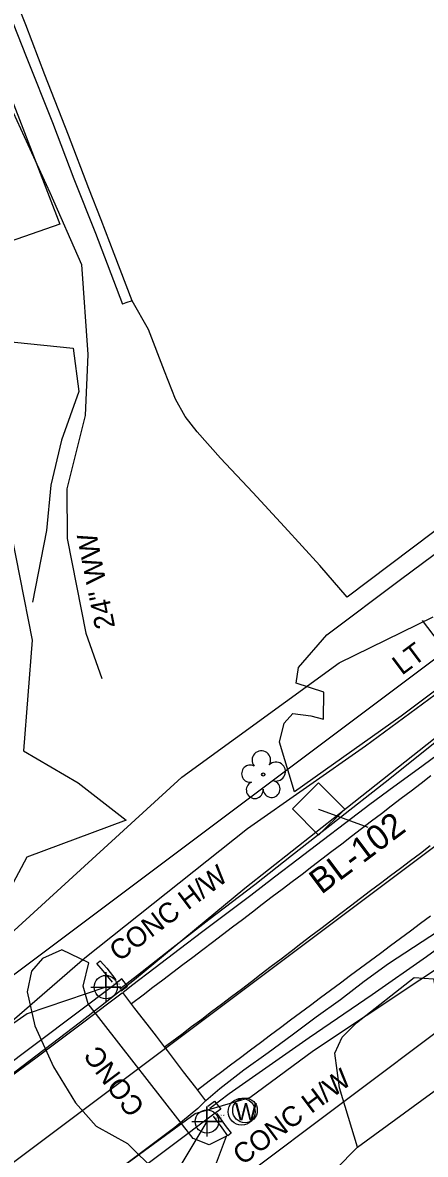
# Model space of a CAD drawing. Extents: x 2186615 to 2188822, y 629899 to 631820.
# Drawn here: x 2187814 to 2187894.7, y 630886.3 to 631112.9 of the extents above; entities that cross this region are included whole.
import ezdxf

# ---------------------------------------------------------------- set-up
doc = ezdxf.new("R2010")
doc.units = 0
for name, color, linetype in [('CTL Secondary Horizontal and Vertical CELL', 7, 'Continuous'), ('CTL Secondary Horizontal and Vertical Text', 7, 'Continuous'), ('CTL Vertical Benchmark Leader', 7, 'Continuous'), ('Exist Guardrail', 7, 'Continuous'), ('Exist Horizontal Alignment', 7, 'Continuous'), ('Exist Other Culture Area Outline', 7, 'Continuous'), ('Exist Other Culture Area Outline Text', 7, 'Continuous'), ('Exist Other Culture Fence Line', 7, 'Continuous'), ('Exist Other Culture Fence Line Text', 7, 'Continuous'), ('Exist Right of Way Line', 7, 'Continuous'), ('Exist Roads Curbs', 7, 'Continuous'), ('Exist Roads EOP', 7, 'Continuous'), ('Exist Roads EOP Other', 7, 'Continuous'), ('Exist Roads EOT', 7, 'Continuous'), ('Exist Structure Major Bridge Seat Cogo Point CELL', 7, 'Continuous'), ('Exist Structure Major Bridge Seat Leader', 7, 'Continuous'), ('Exist Structure Major Bridge WW', 7, 'Continuous'), ('Exist Structure Major Bridge WW Cogo Comment', 7, 'Continuous'), ('Exist Structure Major Bridge WW Text', 7, 'Continuous'), ('Exist Structure Major Deck Tunnel Box Culvert', 7, 'Continuous'), ('Exist Utilities Gas UG Line SUE LOS B', 7, 'Continuous'), ('Exist Utilities Power Pole CELL', 7, 'Continuous'), ('Exist Utilities Power Pole Text', 7, 'Continuous'), ('Exist Utilities Sanitary Sewer Forced Main SUE LOS B', 7, 'Continuous'), ('Exist Utilities Telephone UG FO SUE LOS B', 7, 'Continuous'), ('Exist Utilities Water Manhole CELL', 7, 'Continuous'), ('Exist Utilities Water UG Line SUE LOS B', 7, 'Continuous'), ('Exist Vegetation Hedge Row', 7, 'Continuous'), ('Exist Vegetation Tree CELL', 7, 'Continuous'), ('Exist Vegetation Woods Line', 7, 'Continuous')]:
    doc.layers.add(name, color=color, linetype=linetype)

msp = doc.modelspace()

# ---------------------------------------------------------------- linework, layer by layer
at = {"layer": 'CTL Secondary Horizontal and Vertical CELL'}
msp.add_line((2187873.29, 630955.43), (2187873.29, 630955.43), dxfattribs=at)
msp.add_lwpolyline([(2187868.08, 630955.45), (2187873.32, 630960.69), (2187878.57, 630955.44), (2187873.33, 630950.2)], close=True, dxfattribs=at)
at = {"layer": 'CTL Vertical Benchmark Leader'}
msp.add_line((2187873.29, 630955.43), (2187883.19, 630951.78), dxfattribs=at)
at = {"layer": 'Exist Guardrail'}
for points in [[(2188042.59, 631032.9), (2188030.54, 631024.16), (2188016.07, 631013.69), (2188000.23, 631002.25), (2187980.63, 630988.06), (2187964.45, 630976.33), (2187945.19, 630962.3), (2187928.74, 630950.37), (2187912, 630938.23), (2187894.95, 630925.87), (2187884.09, 630918.25), (2187871.47, 630909.61), (2187859.4, 630901.23), (2187855.44, 630898.44), (2187851.53, 630895.46)], [(2187833.49, 630919.46), (2187837.07, 630922.2), (2187843.61, 630927.3), (2187851.34, 630933.3), (2187860.56, 630940.3), (2187867.93, 630946.1), (2187876.17, 630952.6), (2187887.64, 630961.57), (2187898.7, 630970.45), (2187913.98, 630982.76), (2187928.97, 630994.69), (2187939.72, 631003.5)]]:
    msp.add_lwpolyline(points, dxfattribs=at)
at = {"layer": 'Exist Horizontal Alignment'}
msp.add_line((2187136.41, 630378.11), (2188520.86, 631416.04), dxfattribs=at)
at = {"layer": 'Exist Other Culture Area Outline'}
for points in [[(2187750.73, 631131.73), (2187754.38, 631137.93), (2187762.75, 631146.44), (2187787.59, 631158.3), (2187791.85, 631141.33), (2187804.46, 631116.53), (2187821.46, 631072.54), (2187791.35, 631062.08), (2187778.49, 631068.35), (2187771.08, 631115.01), (2187750.73, 631131.73)], [(2187821.88, 630927.25), (2187817.99, 630925.54), (2187815.81, 630923), (2187814.96, 630918.81), (2187816.47, 630912.02), (2187820.24, 630903.82), (2187824.62, 630896.62), (2187828.79, 630891.96), (2187835.07, 630888.46), (2187840.78, 630882.77), (2187850.88, 630879.29), (2187854.91, 630889.95), (2187851.43, 630888.23), (2187848.23, 630889.48), (2187827.14, 630916.4), (2187826.15, 630919.95), (2187827.29, 630924.63), (2187821.88, 630927.25)], [(2187835.03, 630919.99), (2187833.88, 630921.43), (2187832.7, 630920.52)], [(2187852.49, 630896.95), (2187853.72, 630895.32), (2187852.33, 630894.37)]]:
    msp.add_lwpolyline(points, dxfattribs=at)
msp.add_circle((2187858.59, 630895.1), 2.47, dxfattribs=at)
at = {"layer": 'Exist Other Culture Fence Line'}
msp.add_lwpolyline([(2187792.58, 631147.74), (2187801.82, 631123.05), (2187808.4, 631102.87), (2187819.45, 631078.84), (2187825.81, 631064.45), (2187827.07, 631046.46), (2187826.56, 631034.21), (2187822.88, 631019.53), (2187822.94, 631009.61), (2187826.72, 630990.63), (2187829.88, 630981.56)], dxfattribs=at)
at = {"layer": 'Exist Right of Way Line'}
for p, q in [((2187118.41, 630402.11), (2188502.83, 631440.02)), ((2187154.4, 630354.1), (2188538.85, 631392.04))]:
    msp.add_line(p, q, dxfattribs=at)
at = {"layer": 'Exist Roads Curbs'}
for p, q in [((2187833.75, 630919.03), (2187835.03, 630919.99)), ((2187851.12, 630895.95), (2187852.49, 630896.95))]:
    msp.add_line(p, q, dxfattribs=at)
msp.add_lwpolyline([(2187793.54, 631161.47), (2187796.84, 631152.67), (2187801.21, 631141.09), (2187806.19, 631128.11), (2187811.25, 631114.94), (2187814.74, 631106.11), (2187819.99, 631092.86), (2187824.32, 631081.63), (2187828.62, 631070.74), (2187834.04, 631056.52)], dxfattribs=at)
at = {"layer": 'Exist Roads EOP'}
for points in [[(2187834.08, 630918.72), (2187835.85, 630920.07), (2187840.59, 630923.74), (2187845.37, 630927.36), (2187850.17, 630930.96), (2187854.95, 630934.59), (2187859.73, 630938.22), (2187864.5, 630941.86), (2187869.27, 630945.49), (2187874.05, 630949.13), (2187878.82, 630952.76), (2187883.6, 630956.39), (2187888.43, 630959.94), (2187893.28, 630963.48), (2187898.13, 630967.01)], [(2187897.38, 630931.01), (2187892.37, 630927.71), (2187887.34, 630924.44), (2187882.5, 630920.9), (2187877.75, 630917.23), (2187872.88, 630913.73), (2187868.05, 630910.16), (2187863.22, 630906.61), (2187858.33, 630903.13), (2187853.53, 630899.39), (2187850.72, 630897.03)]]:
    msp.add_lwpolyline(points, dxfattribs=at)
at = {"layer": 'Exist Roads EOP Other'}
for points in [[(2187835.99, 631057.2), (2187832.38, 631066.61), (2187829.78, 631073.37), (2187827.33, 631079.65), (2187823.24, 631090.34), (2187818.48, 631102.46), (2187814.66, 631112.43), (2187811.6, 631120.28), (2187807.65, 631130.42), (2187803.81, 631140.26), (2187800.02, 631150.43), (2187796.16, 631160.6), (2187794.84, 631164.12), (2187792.02, 631171.25), (2187785.09, 631189.07)], [(2188041.82, 631120.35), (2188026.58, 631108.99), (2188015.21, 631100.2), (2188006.81, 631093.93), (2187989.59, 631081.15), (2187980.04, 631073.87), (2187966.12, 631063.56), (2187954.13, 631054.4), (2187938.28, 631042.55), (2187922.6, 631030.98), (2187908.64, 631020.51), (2187896.45, 631010.96), (2187879.08, 630997.86), (2187873.59, 631004.21), (2187866.53, 631011.95), (2187860.14, 631018.79), (2187853.68, 631025.69), (2187849, 631030.96), (2187846.61, 631033.99), (2187844.68, 631037.52), (2187842.44, 631043.11), (2187839.28, 631051.45), (2187835.99, 631057.2)], [(2187835.99, 631057.2), (2187834.72, 631056.79), (2187834.04, 631056.52)]]:
    msp.add_lwpolyline(points, dxfattribs=at)
at = {"layer": 'Exist Roads EOT'}
for points in [[(2187835.83, 630916.47), (2187838.16, 630918.23), (2187840.15, 630919.75), (2187842.14, 630921.26), (2187844.14, 630922.77), (2187846.13, 630924.28), (2187848.12, 630925.79), (2187850.11, 630927.3), (2187852.1, 630928.81), (2187854.09, 630930.33), (2187856.08, 630931.84), (2187858.07, 630933.35), (2187860.06, 630934.86), (2187862.05, 630936.37), (2187864.04, 630937.89), (2187866.04, 630939.4), (2187868.03, 630940.91), (2187870.02, 630942.42), (2187872.01, 630943.94), (2187874, 630945.45), (2187875.98, 630946.97), (2187877.97, 630948.48), (2187879.96, 630950), (2187881.94, 630951.52), (2187883.93, 630953.04), (2187885.92, 630954.55), (2187887.9, 630956.07), (2187889.89, 630957.59), (2187891.88, 630959.11), (2187893.87, 630960.62), (2187895.85, 630962.14)], [(2187842.46, 630907.8), (2187843.9, 630908.89), (2187845.9, 630910.38), (2187847.9, 630911.88), (2187849.91, 630913.37), (2187851.91, 630914.87), (2187853.91, 630916.37), (2187855.9, 630917.88), (2187857.89, 630919.4), (2187859.88, 630920.92), (2187861.86, 630922.43), (2187863.85, 630923.95), (2187865.83, 630925.47), (2187867.82, 630926.99), (2187869.81, 630928.51), (2187871.79, 630930.03), (2187873.78, 630931.54), (2187875.77, 630933.06), (2187877.76, 630934.57), (2187879.76, 630936.08), (2187881.75, 630937.58), (2187883.75, 630939.09), (2187885.74, 630940.59), (2187887.74, 630942.1), (2187889.73, 630943.6), (2187891.73, 630945.11), (2187893.73, 630946.61), (2187895.72, 630948.12)], [(2187895.79, 630933.98), (2187893.78, 630932.5), (2187891.77, 630931.01), (2187889.76, 630929.52), (2187887.75, 630928.03), (2187885.75, 630926.54), (2187883.74, 630925.06), (2187881.73, 630923.57), (2187879.72, 630922.08), (2187877.71, 630920.59), (2187875.71, 630919.1), (2187873.7, 630917.61), (2187871.69, 630916.12), (2187869.69, 630914.62), (2187867.68, 630913.13), (2187865.68, 630911.64), (2187863.68, 630910.14), (2187861.68, 630908.64), (2187859.68, 630907.14), (2187857.68, 630905.63), (2187855.68, 630904.13), (2187853.68, 630902.63), (2187851.68, 630901.13), (2187849.68, 630899.63), (2187849.08, 630899.16)]]:
    msp.add_lwpolyline(points, dxfattribs=at)
at = {"layer": 'Exist Structure Major Bridge Seat Cogo Point CELL'}
for points in [[(2187827.7, 630919.78), (2187833.7, 630919.78), (2187830.7, 630919.78), (2187830.7, 630922.78), (2187830.7, 630916.78)], [(2187847.96, 630892.87), (2187853.96, 630892.87), (2187850.96, 630892.87), (2187850.96, 630895.87), (2187850.96, 630889.87)]]:
    msp.add_lwpolyline(points, dxfattribs=at)
for centre in [(2187830.7, 630919.78), (2187850.96, 630892.87)]:
    msp.add_circle(centre, 2.34, dxfattribs=at)
at = {"layer": 'Exist Structure Major Bridge Seat Leader'}
for points in [[(2187830.7, 630919.78), (2187814.95, 630914.46), (2187810.04, 630911)], [(2187850.96, 630892.87), (2187841.54, 630877.16), (2187836.65, 630873.69)]]:
    msp.add_lwpolyline(points, dxfattribs=at)
at = {"layer": 'Exist Structure Major Bridge WW'}
for points in [[(2187832.01, 630920.77), (2187830.19, 630923.05), (2187828.88, 630924.52), (2187829.54, 630925.05), (2187830.88, 630923.57), (2187832.71, 630921.21)], [(2187852.93, 630894.46), (2187854.64, 630892.08), (2187855.82, 630890.53), (2187855.17, 630890.01), (2187853.99, 630891.62), (2187852.28, 630893.97)]]:
    msp.add_lwpolyline(points, dxfattribs=at)
at = {"layer": 'Exist Structure Major Deck Tunnel Box Culvert'}
for p, q in [((2187582.05, 630732.05), (2187832.7, 630920.52)), ((2187852.33, 630894.37), (2187601.73, 630705.99))]:
    msp.add_line(p, q, dxfattribs=at)
for points in [[(2187787.85, 630884.07), (2187792.64, 630887.67), (2187797.44, 630891.28), (2187802.24, 630894.88), (2187807.05, 630898.47), (2187811.85, 630902.06), (2187816.66, 630905.65), (2187821.46, 630909.24), (2187826.27, 630912.84), (2187831.07, 630916.43), (2187834, 630918.66)], [(2187834.04, 630918.69), (2187836.48, 630915.52), (2187838.92, 630912.35), (2187840.77, 630909.93), (2187842.42, 630907.79), (2187842.97, 630907.07), (2187843.79, 630906.01), (2187846.23, 630902.83), (2187848.66, 630899.66), (2187850.7, 630897.01)], [(2187850.69, 630897), (2187849.14, 630895.48), (2187844.52, 630891.65), (2187839.72, 630888.05), (2187834.93, 630884.45)]]:
    msp.add_lwpolyline(points, dxfattribs=at)
at = {"layer": 'Exist Utilities Gas UG Line SUE LOS B'}
msp.add_lwpolyline([(2187773.44, 630905.16), (2187806.03, 630925.44), (2187845.96, 630961.84), (2187877.43, 630984.73), (2187896.27, 630993.91)], dxfattribs=at)
at = {"layer": 'Exist Utilities Power Pole CELL'}
msp.add_line((2187897.56, 630988.68), (2187894.15, 630993.16), dxfattribs=at)
at = {"layer": 'Exist Utilities Sanitary Sewer Forced Main SUE LOS B'}
msp.add_lwpolyline([(2187639.4, 630737.18), (2187658.16, 630751.34), (2187676.41, 630765.17), (2187695.58, 630779.55), (2187713.95, 630793.24), (2187732.6, 630807.47), (2187751.11, 630821.21), (2187774.55, 630838.89), (2187793.19, 630853.01), (2187817.13, 630870.75), (2187832.54, 630882.73), (2187848.61, 630894.45), (2187859.56, 630897.68), (2187872.29, 630907.08), (2187904.19, 630928.23), (2187917.85, 630937.14), (2187951.64, 630961.53), (2187983.48, 630985.87), (2188013.42, 631007.09), (2188037.93, 631025.04), (2188052.05, 631035.58)], dxfattribs=at)
at = {"layer": 'Exist Utilities Telephone UG FO SUE LOS B'}
for points in [[(2187859.07, 630951.55), (2187882.76, 630968.07), (2187903.06, 630983.05), (2187928.09, 631001.38), (2187948.02, 631018.93), (2187983.82, 631042.28), (2188016.23, 631068.08), (2188049.6, 631091.76), (2188063.06, 631102.31), (2188071.06, 631108.58), (2188069.02, 631112.49), (2188069.37, 631119.05), (2188075.07, 631125.87), (2188092.55, 631139.53), (2188117.88, 631159.65), (2188156.33, 631187.11), (2188185.96, 631206.22), (2188210.21, 631221.29), (2188233.48, 631238.15), (2188251.53, 631251.3), (2188274.73, 631269.24), (2188303.07, 631290.83)], [(2187785.72, 630883.08), (2187793.24, 630892.77), (2187804.79, 630906.92), (2187826.49, 630925.65), (2187859.07, 630951.55)]]:
    msp.add_lwpolyline(points, dxfattribs=at)
at = {"layer": 'Exist Utilities Water Manhole CELL'}
msp.add_line((2187857.92, 630894.83), (2187857.92, 630894.83), dxfattribs=at)
msp.add_circle((2187857.92, 630894.83), 2.69, dxfattribs=at)
at = {"layer": 'Exist Utilities Water UG Line SUE LOS B'}
msp.add_line((2187836.42, 630921.29), (2187858.58, 630939.62), dxfattribs=at)
for points in [[(2187858.58, 630939.62), (2187877.52, 630954.54), (2187897.98, 630970.72), (2187926.28, 630993.39), (2187953.07, 631014.11), (2187986.18, 631039.09), (2188018.97, 631064.16), (2188052.07, 631088.62), (2188105.21, 631128.41), (2188127.75, 631145.3), (2188164.18, 631174.44), (2188192.98, 631196.26), (2188209.23, 631208.45), (2188231.7, 631224.75), (2188257.48, 631242.51), (2188270.74, 631252.18), (2188280.66, 631259.06), (2188311.2, 631281.93)], [(2187641.11, 630774.22), (2187678.52, 630802.38), (2187706.44, 630823.47), (2187734.48, 630844.42), (2187753.27, 630858.4), (2187771.59, 630872.2), (2187805.1, 630897.31), (2187825.65, 630912.81), (2187836.42, 630921.29)]]:
    msp.add_lwpolyline(points, dxfattribs=at)
at = {"layer": 'Exist Vegetation Hedge Row'}
for points in [[(2187803.42, 631013.45), (2187801.43, 631025.46), (2187800.36, 631037.33), (2187803.38, 631047.03), (2187806.46, 631049.51), (2187824.13, 631047.7), (2187825.29, 631039), (2187821.84, 631029.29), (2187819.66, 631020.29), (2187818.8, 631011.19), (2187815.99, 630996.82)], [(2187910.11, 630989.16), (2187889.9, 630974.05), (2187868.5, 630958.85), (2187865.5, 630968.84), (2187866.46, 630972.65), (2187868.16, 630974.56), (2187871.75, 630974.06), (2187874.34, 630973.45), (2187874.37, 630978.85), (2187868.81, 630980.65), (2187869.28, 630983.75), (2187874.96, 630990.3), (2187889.76, 631001.38), (2187909.69, 631016.19)], [(2187881.14, 630887.73), (2187877.53, 630899.64), (2187876.58, 630906.58), (2187878.04, 630909.79), (2187880.92, 630912.64), (2187892.5, 630921.69), (2187896.34, 630921.47), (2187900, 630901.47)]]:
    msp.add_lwpolyline(points, dxfattribs=at)
at = {"layer": 'Exist Vegetation Tree CELL'}
msp.add_line((2187862.24, 630962.35), (2187862.24, 630962.35), dxfattribs=at)
msp.add_circle((2187862.24, 630962.35), 0.326, dxfattribs=at)
for centre, radius, start, end in [((2187861.86, 630965.23), 1.86, 330.1651, 219.7134), ((2187859.64, 630962.51), 1.73, 62.6636, 279.3457), ((2187864.79, 630962.94), 1.9, 257.1011, 134.1999), ((2187863.91, 630959.45), 1.7, 181.2822, 74.56), ((2187860.54, 630959.23), 1.69, 111.5671, 6.231)]:
    msp.add_arc(centre, radius, start, end, dxfattribs=at)
at = {"layer": 'Exist Vegetation Woods Line'}
for points in [[(2188336.81, 631162.74), (2188304.67, 631140.79), (2188253.49, 631107.84), (2188202.91, 631074.1), (2188139.41, 631031.67), (2188093.1, 631000.83), (2188032.1, 630960.3), (2187970.81, 630919.03), (2187899.6, 630870.56), (2187878.91, 630858.57), (2187866.57, 630849.5), (2187856.84, 630841.46), (2187846.68, 630832.19), (2187829.94, 630827.76), (2187807.52, 630819.83), (2187838.54, 630838.9), (2187846.29, 630845.15), (2187849.33, 630854.22), (2187863.66, 630870.01), (2187881.14, 630887.73), (2187900, 630901.47)], [(2187814.88, 630945.78), (2187811.02, 630938.54), (2187806.04, 630934.48), (2187796.3, 630927.68), (2187779.96, 630930.54), (2187771.48, 630943.56), (2187761.24, 630958.94), (2187762.68, 630976.11), (2187765.49, 630986.71), (2187782.35, 630974.15), (2187801.09, 630988.73), (2187793.43, 631006.17), (2187794, 631017.17), (2187811, 631014.36), (2187815.94, 630989.22), (2187814.24, 630967.11), (2187825.16, 630960.69), (2187834.77, 630953.2), (2187814.88, 630945.78)]]:
    msp.add_lwpolyline(points, dxfattribs=at)

# ---------------------------------------------------------------- texts
at = {"layer": 'CTL Secondary Horizontal and Vertical Text'}
msp.add_text('BL-102', height=5, rotation=36.8593, dxfattribs=at).set_placement((2187873.89, 630938.22))
at = {"layer": 'Exist Other Culture Area Outline Text'}
msp.add_text('CONC', height=4, rotation=126.8593, dxfattribs=at).set_placement((2187838.69, 630895.8))
at = {"layer": 'Exist Other Culture Fence Line Text'}
msp.add_text('24" WW', height=4, rotation=101.248, dxfattribs=at).set_placement((2187832.58, 630991.89))
at = {"layer": 'Exist Structure Major Bridge WW Cogo Comment'}
for s, p in [('BL*3119', (2187832.26, 630920.27)), ('EL*3119', (2187832.96, 630920.71)), ('EL*3119', (2187852.53, 630893.47)), ('BL*3119', (2187853.18, 630893.96))]:
    msp.add_text(s, height=0.25, dxfattribs=at).set_placement(p)
at = {"layer": 'Exist Structure Major Bridge WW Text'}
for p in [(2187833.33, 630924.74), (2187858.07, 630883.98)]:
    msp.add_text('CONC H/W', height=4, rotation=36.8593, dxfattribs=at).set_placement(p)
at = {"layer": 'Exist Utilities Power Pole Text'}
msp.add_text('LT', height=4, rotation=36.8593, dxfattribs=at).set_placement((2187890.03, 630982.1))
at = {"layer": 'Exist Utilities Water Manhole CELL'}
msp.add_text('W', height=3.5, dxfattribs=at).set_placement((2187856.57, 630893.08))

doc.saveas('drawing.dxf')
